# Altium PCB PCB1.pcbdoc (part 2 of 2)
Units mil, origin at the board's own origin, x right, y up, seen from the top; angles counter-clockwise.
Board outline 2401.6 x 2401.6 mil, 2 copper layers (Top Layer, Bottom Layer), stack 62.2 mil thick; 60 components, 46 nets, 313 pads, 160 vias.
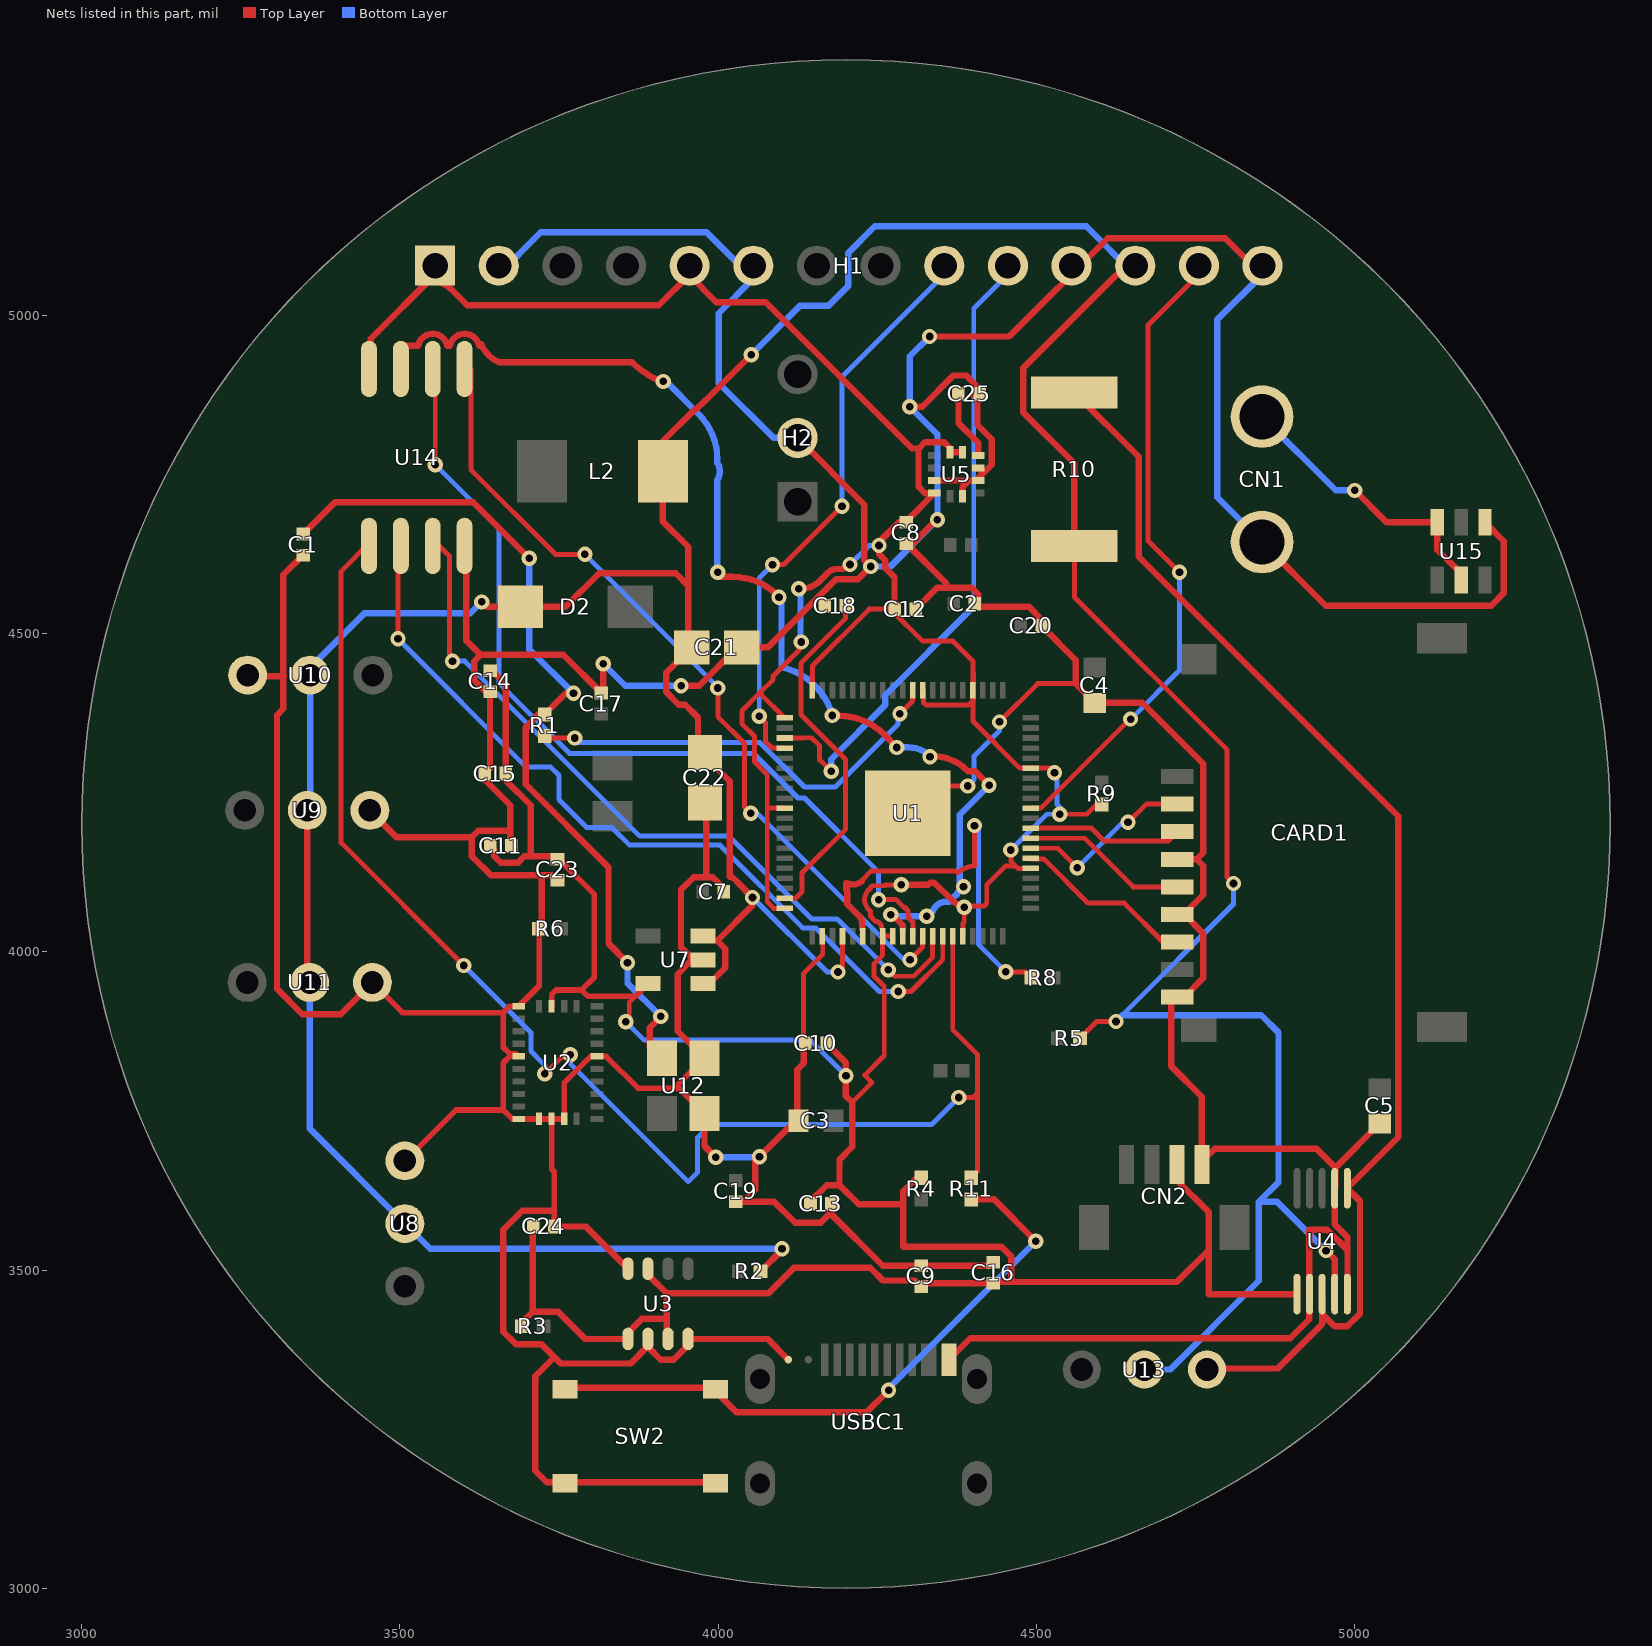
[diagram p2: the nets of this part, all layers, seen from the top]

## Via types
v1: diameter 24, hole 12, Top Layer to Bottom Layer, 160 vias

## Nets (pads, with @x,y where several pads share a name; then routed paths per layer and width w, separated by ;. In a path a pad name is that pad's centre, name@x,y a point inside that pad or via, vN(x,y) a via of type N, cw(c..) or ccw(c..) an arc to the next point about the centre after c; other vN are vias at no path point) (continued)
$1N402: H1.9 U1.44 | length 901.6
  Top Layer w7.8: v1(4064.5,4370.1) 4074.5,4360.1 4074.5,4330.1 4084.5,4320.1 U1.44@4104.5,4320.1 ; v1(4085.4,4608.2) 4102.5,4608.2 v1(4194.5,4700.1)
  Bottom Layer w7.8: v1(4064.5,4370.1) 4064.5,4587.2 v1(4085.4,4608.2) ; v1(4194.5,4700.1) 4194.5,4903.6 H1.9@4354.3,5063.4
$1N403: H1.10 U1.43 | length 1001.4
  Top Layer w7.8: U1.43@4104.5,4335.9 4131.5,4335.9 4131.9,4336.3 4146.6,4336.3 4159.4,4323.5 4159.4,4301.7 v1(4177.5,4283.6)
  Bottom Layer w7.8: 4401.5,4542.7 4401.5,5010.6 H1.10@4454.3,5063.4
  Bottom Layer w10: v1(4177.5,4283.6) 4177.5,4302.8 4262.5,4387.8 4262.5,4403.2 4398.6,4539.3 4398.6,4539.6 ccw(c4395.5,4542.7) 4399.9,4542.7
$1N404: H1.13 U1.11 | length 997.6
  Top Layer w7.8: U1.11@4490.9,4225.6 4506.6,4225.6 4646.6,4365.6 v1(4647.9,4365.6) ; v1(4724.8,4596.1) 4675.6,4645.3 4675.6,4984.7 H1.13@4754.3,5063.4
  Bottom Layer w7.8: v1(4647.9,4365.6) 4724.8,4442.6 v1(4724.8,4596.1)
$1N405: CARD1.5 U1.8 | length 262.2
  Top Layer w7.8: U1.8@4490.9,4178.4 4575.7,4178.4 4652,4102.1 CARD1.5@4721.5,4102.1
$1N406: CARD1.3 U1.9 | length 244.9
  Top Layer w7.8: U1.9@4490.9,4194.2 4586.5,4194.2 4606.5,4174.2 4707,4174.2 CARD1.3@4721.5,4188.7
$1N409: CARD1.2 U1.7 | length 284.9
  Top Layer w7.8: U1.7@4490.9,4162.7 4533.6,4162.7 v1(4564.3,4131.9) ; v1(4643.9,4203.4) 4672.5,4232 CARD1.2@4721.5,4232
  Bottom Layer w7.8: v1(4564.3,4131.9) 4635.7,4203.4 v1(4643.9,4203.4)
$1N413: R8.1 U1.66 | length 655.5
  Top Layer w7.8: U1.66@4225.3,4026.1 U1.66@4226.8,4024.6 ; 4225.3,4111.8 4240.6,4127.2 4373.4,4127.2 4376.3,4124.3 ; 4376.25,4124.23 cw(c4406.4,4088.3) 4402.31,4135.02 ; 4402.6,4135.1 v1(4402.6,4198.3) ; v1(4451.9,3968.6) 4483.3,3968.6 R8.1@4492.5,3959.4
  Top Layer w10: 4201.25,4108.11 ccw(c4211.3,4128.8) 4225.87,4111 ; 4201.3,4098.5 4201.3,4108.1 ; 4201.28,4098.56 cw(c4187.9,4092) 4202.8,4092 4202.8,4074.6 4221.6,4055.8 ; 4221.64,4055.84 cw(c4211.1,4045.3) 4225.9,4046.99 4226.2,4046.6 cw(c4225.3,4045.7) 4226.6,4045.7 U1.66@4226.6,4035.4
  Bottom Layer w7.8: v1(4402.6,4198.3) 4408.6,4192.3 4408.6,4012 v1(4451.9,3968.6)
$1N418: CN1.2 U15.3 U15.5 | length 450.2
  Top Layer w10: v1(4999.9,4724.9) 5049.9,4674.9 U15.3@5129.9,4674.9 5129.9,4631.8 5167.3,4594.4 U15.5@5167.3,4584.4
  Bottom Layer w10: CN1.2@4854.4,4840.7 4970.2,4724.9 v1(4999.9,4724.9)
$1N424: R1.1 U1.30 | length 691.8
  Top Layer w7.8: R1.1@3727.6,4338.9 3730.7,4335.8 v1(3774.5,4335.8) ; v1(4285.5,4374) 4305.5,4394 U1.30@4305.5,4411
  Bottom Layer w7.8: v1(3774.5,4335.8) 3781.3,4328.9 4065.5,4328.9 4135.5,4258.9 4183.8,4258.9 4282.7,4357.9 4282.7,4371.2 v1(4285.5,4374)
$1N425: C1.1 R1.2 U12.1 | length 1373.9
  Top Layer w10: C1.1@3347.9,4656.4 3397.9,4706.4 3615.3,4706.4 v1(3703.3,4618.4) ; v1(3772.8,4406) 3760.6,4406 R1.2@3727.6,4373 3717.6,4373 3697.6,4353 3697.6,4263 3827.6,4133 3827.6,4013 v1(3857.6,3983) ; v1(3909.8,3898.5) 3909.8,3898 3892.6,3880.8 3892.6,3851.7 U12.1@3911.5,3832.8
  Bottom Layer w10: v1(3703.3,4618.4) 3703.3,4475.6 v1(3772.8,4406) ; v1(3857.6,3983) 3857.6,3950.8 v1(3909.8,3898.5)
$1N433: C8.1 C9.1 C10.1 C11.1 C12.1 C13.1 C14.1 C15.1 C16.1 C23.1 C24.1 CN2.2 H1.1 H1.5 R3.2 R4.2 R9.2 U1.5 U1.15 U1.24 U1.29 U1.40 U1.41 U1.50 U1.60 U1.68 U1.69 U1.76 U2.4 U3.2 U3.6 U3.8 U4.6 U5.5 U5.6 U5.10 U7.5 U14.8 | length 7991
  Top Layer w7.8: v1(3854.9,3890) 3860.3,3895.3 3860.3,3920.7 3869.6,3930 ; U1.60@4104.2,4068.4 4087.1,4068.4 4077.1,4078.4 4077.1,4228.4 ; U1.50@4104.5,4225.6 4079.9,4225.6 4077.1,4228.4 ; U1.41@4104.5,4367.4 4067.1,4404.7 4067.1,4408.4 ; v1@4127,4486.3 4127,4473.8 4086.4,4433.2 4086.4,4427.6 4067.1,4408.4 ; U1.40@4148.1,4411 4148.1,4449.3 4237.1,4538.4 C12.1@4277.1,4538.4 4277.1,4532.1 4321.3,4488 4368.8,4488 4400,4456.8 4400,4439.2 ; 4210.6,3763.5 4241.4,3794.4 4241.4,3794.9 4230,3806.3 4260.9,3837.2 4260.9,3945.4 4245,3961.3 4245,3981.3 4258.3,3994.6 U1.68@4258.3,4024.6 ; 4239.3,4055.6 4239.3,4064.1 ; 4239.31,4064.05 cw(c4252,4081.9) 4239.31,4099.75 ; 4239.3,4099.8 4239.3,4101.2 4241.9,4103.8 4261.1,4103.8 4262.5,4105.2 v1(4287.5,4105.2) ; 4240.6,4054.6 4247.7,4047.5 ; 4247.73,4047.57 cw(c4246.9,4037.7) 4256.8,4037.7 ccw(c4261.8,4037.7) U1.68@4258.26,4034.16 ; U1.68@4256.8,4026.1 U1.68@4258.3,4024.6 ; U1.68@4258.2,4034.1 U1.68@4258.4,4033.9 ; U1.69@4274.1,4024.6 U1.68@4258.3,4024.6 ; U1.29@4321.3,4411 4322.6,4409.7 4322.6,4391.5 4326.1,4388 4393.5,4388 4400,4394.5 ; U1.76@4384.3,4024.6 4384.3,4044.6 4386.6,4046.9 v1(4386.6,4070) ; v1(4386.6,4070) ccw(c4389.9,4070.7) v1@4393.02,4072.05 ; v1@4393,4072.1 4418.1,4072.1 ; 4418.1,4072.04 ccw(c4404.5,4089.2) 4421.66,4075.6 ; 4421.9,4075.9 4421.9,4105.4 4451.6,4135.1 4466.9,4135.1 ; v1(4459.8,4159.9) 4459.8,4142.3 4466.9,4135.1 ; U1.5@4490.9,4131.2 4470.9,4131.2 4466.9,4135.1 ; v1(4528.4,4281.2) 4520.9,4288.6 U1.15@4490.9,4288.6 4473.9,4288.6 4400,4362.5 4400,4394.5 ; v1(4536.8,4216.1) 4579.1,4216.1 4598,4235 R9.2@4603.5,4235 ; 4067.1,4408.4 4037.1,4378.4 4037.1,4358.4 4057.1,4338.4 4057.1,4298.4 4077.1,4278.4 4077.1,4228.4 ; 4400,4394.5 U1.24@4400,4411 4400,4439.2 ; 4400,4394.5 4401.3,4395.8 4401.3,4438 4400,4439.2
  Top Layer w8.9: U2.4@3738.3,3914.5 3738.3,3932.7 3745.5,3940 3785.5,3940 ; C23.1@3747.6,4145.5 3755.5,4140 3805.5,4090 3805.5,3960 3785.5,3940 ; U7.5@3889.6,3950 3869.6,3930 3795.5,3930 3785.5,3940
  Top Layer w9.9: H1.5@3954.3,5063.4 3997.1,5020.6 4074.8,5020.6 4304.8,4790.6 4314.8,4790.6 ; C8.1@4295.8,4674.6 4295.8,4676.7 U5.10@4339.6,4720.6 4324.8,4720.6 4314.8,4730.6 4314.8,4790.6 ; U5.5@4383.9,4784.6 U5.6@4364.3,4784.6 4364.3,4791.2 4354.8,4800.6 4324.8,4800.6 4314.8,4790.6
  Top Layer w10: U14.8@3454.2,4922.9 3454.2,4963.3 H1.1@3554.3,5063.4 ; H1.1@3550.7,5053.2 cw(c3550.7,5010.6) 3580.82,5040.72 ; 3580.9,5040.7 3606,5015.6 ; 3606.4,5015.6 3906.4,5015.6 H1.5@3954.3,5063.4 ; C14.1@3641.6,4441.4 3645,4441.4 3666.2,4420.1 C15.1@3666.2,4280.1 3666.2,4269.2 3705.5,4230 3705.5,4150 ; C11.1@3641.7,4166.5 3648.2,4160 3648.2,4150 3658.2,4140 3685.5,4140 3695.5,4150 3705.5,4150 ; R3.2@3691.7,3411.5 3691.7,3417.9 3708.4,3434.6 ; C24.1@3709.3,3568.5 3708.4,3567.6 3708.4,3434.6 ; C23.1@3755.5,4140 3745.5,4150 3705.5,4150 ; U3.2@3889.8,3502.1 3889.8,3492.9 3919,3463.7 ; U3.6@3921.3,3391.8 3919,3394.2 3919,3423.7 ; v1@4125,4569.1 ccw(c4125,4620.5) 4161.35,4584.15 ; C13.1@4145,3604.5 4145,3607.9 4170.6,3633.5 4190.6,3633.5 ; 4161.3,4584.2 4173.9,4596.7 cw(c4185.2,4585.4) 4185.2,4601.4 4192.4,4601.4 ccw(c4192.4,4618.8) 4204.7,4606.5 v1@4206.9,4608.7 ; C10.1@4170.2,3856.4 4200.6,3826 4200.6,3773.5 4210.6,3763.5 4210.6,3693.5 4190.6,3673.5 4190.6,3633.5 ; C12.1@4277.1,4538.4 4277.1,4588.4 4262.7,4602.9 4262.7,4614.9 4252.6,4625 v1(4252.6,4638.4) 4252.6,4643.9 4283.4,4674.6 C8.1@4295.8,4674.6 ; v1(4287.5,4105.2) 4302.4,4105.2 4302.8,4105.6 4321.8,4105.6 4322.2,4105.2 4329.7,4105.2 4332.1,4107.7 ; R4.2@4319,3645.1 4312.1,3645.1 4290.6,3623.5 4290.6,3603.5 ; 4334,4108.7 4339.6,4108.7 4368.3,4080 ; 4368.27,4080.07 ccw(c4386.8,4098.6) v1@4386.8,4072.4 ; CN2.2@4720.5,3666 4720.5,3641.3 4770.5,3591.3 4770.5,3531.3 ; U4.6@4909.5,3462.3 4770.5,3462.3 4770.5,3531.3 ; 3708.4,3434.6 3748.4,3434.6 3791.1,3391.8 U3.8@3858.4,3391.8 3858.4,3401.8 3880.2,3423.7 3919,3423.7 ; 3919,3423.7 3919,3463.7 ; 3919,3463.7 4079,3463.7 4119,3503.7 4239,3503.7 4259,3483.7 4309,3483.7 C9.1@4319,3473.7 4324.6,3479.3 C16.1@4432.4,3479.3 4434.3,3481.3 4460.5,3481.3 ; 4190.6,3633.5 4220.6,3603.5 4290.6,3603.5 ; 4290.6,3603.5 4290.6,3536.7 4445.1,3536.7 4460.5,3521.3 4460.5,3481.3 ; 4460.5,3481.3 4720.5,3481.3 4770.5,3531.3
  Bottom Layer w7.8: v1(3854.9,3890) 3883.6,3861.3 4144.8,3861.3 v1(4200.7,3805.3) ; v1(4207.1,4608.4) 4237.1,4638.4 v1(4252.6,4638.4) ; v1(4459.8,4159.9) 4516,4216.1 v1(4536.8,4216.1) 4536.8,4227.5 4532.4,4231.8 4532.4,4277.2 v1(4528.4,4281.2)
  Bottom Layer w10: v1@4127.13,4568.43 cw(c4121.9,4563.2) v1@4129.3,4563.2 ; v1@4129.4,4486 v1@4129.4,4563.2
  other v1: 4130.7,4486.7 4126.7,4570.3
$1N435: R10.1 U4.1 U4.8 U13.1 | length 2063.9
  Top Layer w10: R10.1@4559.5,4878.8 4660.7,4777.6 4660.7,4620.6 5068.3,4213 5068.3,3708.5 U4.1@4988.3,3628.5 5008.3,3608.5 5008.3,3431.6 4988.3,3411.6 4968.3,3411.6 4948.9,3430.9 U4.8@4948.9,3462.3 4948.9,3415.4 4878.9,3345.4 4769.7,3345.4 U13.1@4768,3343.8
$1N438: R11.1 U1.75 U14.1 | length 2261.3
  Top Layer w7.8: U14.1@3454.2,4645 3407.7,4597.8 3407.7,4171.1 v1(3600.4,3978.4) ; v1(3727.7,3808.4) 3757.7,3838.4 v1(3767.7,3838.4) ; U1.75@4368.5,4024.6 4368.5,3877.6 4407.7,3838.4 4407.7,3778.4 ; v1(4378,3771.2) 4400.5,3771.2 4407.7,3778.4 ; R11.1@4397.7,3645.1 4407.7,3655.1 4407.7,3778.4
  Bottom Layer w7.8: v1(3600.4,3978.4) 3705.9,3872.9 3705.9,3843.8 3727.7,3821.9 v1(3727.7,3808.4) ; v1(3767.7,3838.4) 3767.7,3824.1 3952.9,3638.9 3967.7,3653.7 3967.7,3708.4 3987.7,3728.4 4335.2,3728.4 v1(4378,3771.2)
$1N439: R11.2 SW2.1 SW2.2 | length 1003.6
  Top Layer w10: SW2.1@3754.2,3312.8 3756.8,3315.4 3989.8,3315.4 4028.8,3276.4 4233.1,3276.4 v1(4267.7,3311) ; R11.2@4397.7,3611 4433.3,3611 v1(4498.9,3545.4)
  Bottom Layer w10: v1(4267.7,3311) 4267.7,3314.2 v1(4498.9,3545.4)
$1N444: C18.1 U1.59 | length 567.4
  Top Layer w7.8: U1.59@4104.5,4083.9 4121.5,4083.9 4131.5,4093.9 4131.5,4123.9 4200.3,4192.7 4200.3,4302.1 4130.3,4372.1 4130.3,4453.9 4200.3,4523.9 C18.1@4200.3,4543.7
$1N448: C21.1 C22.1 D2.1 H1.12 L2.2 R2.2 R5.1 R10.2 U1.64 U4.9 U7.1 U7.3 U8.2 U9.2 U10.2 U11.2 U13.2 | length 7115.7
  Top Layer w7.8: v1(4188.3,3968.2) 4195.3,3975.2 U1.64@4195.3,4024.6 ; R10.2@4559.5,4637.4 4559.5,4557.4 4799.5,4317.4 4799.5,4117.4 v1(4809.5,4107.4) ; R5.1@4568.3,3864.3 4594.5,3890.5 v1(4624.9,3890.5)
  Top Layer w10: U9.2@3354.4,4222.1 3354.4,3955.8 U11.2@3358.4,3951.8 ; v1(3628.6,4549.7) 3636.4,4541.9 D2.1@3689.2,4541.9 3760.1,4541.9 3813.1,4594.8 3933.1,4594.8 3953.1,4574.8 ; U7.1@3976.2,3950 3981,3954.8 3990.9,3954.8 4010.9,3974.8 4010.9,4004.8 3998.3,4017.4 4054,4073.1 v1(4054,4085.4) 4029.7,4109.7 4029.7,4109.9 4021.4,4118.2 4018.3,4118.2 4018.3,4268.2 C22.1@3968.3,4318.2 ; C22.1@3979.1,4313.1 3974,4318.2 C22.1@3968.3,4318.2 ; v1(4051.8,4938.2) 3979.4,4865.9 3979.3,4865.9 3965.8,4852.4 3963.6,4852.4 3913.1,4801.9 L2.2@3913.1,4754.8 3913.1,4676.1 3953.1,4636.1 3953.1,4483.5 C21.1@3958.3,4478.2 3918.3,4438.2 3918.3,4408.2 3938.3,4388.2 3948.3,4388.2 3968.3,4368.2 C22.1@3968.3,4318.2 ; R2.2@4066.7,3498.2 4100.2,3531.6 v1(4100.2,3533.4) ; R10.2@4559.5,4637.4 4559.5,4767.3 4479.5,4847.3 4479.5,4917.3 4625.5,5063.4 H1.12@4654.3,5063.4 ; v1(4954.8,3530.6) 4968.6,3516.8 U4.9@4968.6,3462.3
  Bottom Layer w7.8: v1(4054,4085.4) 4171.2,3968.2 v1(4188.3,3968.2) ; 4634.6,3900.1 4809.5,4075 v1(4809.5,4107.4)
  Bottom Layer w10: U9.2@3354.4,4222.1 3359.1,4226.7 3359.1,4446.6 3444.4,4531.9 3610.7,4531.9 v1(3628.6,4549.7) ; U11.2@3358.4,3951.8 3358.4,3722.5 U8.2@3507.8,3573 3547.4,3533.4 v1(4100.2,3533.4) ; v1(4051.8,4938.2) 4128.6,5015.1 4173.3,5015.1 4204.3,5046 4204.3,5097.9 4246.1,5139.7 4578,5139.7 H1.12@4654.3,5063.4 ; v1(4624.9,3890.5) 4634.6,3900.1 4853.3,3900.1 4880.2,3873.2 4880.2,3638.1 4849.5,3607.4 ; U13.2@4669.6,3343.8 4710.1,3343.8 4849.5,3483.2 4849.5,3607.4 ; v1(4954.8,3530.6) 4878,3607.4 4849.5,3607.4
$1N449: U1.74 U14.2 | length 1321.7
  Top Layer w7.8: v1(3496.9,4491.9) 3496.9,4637.7 U14.2@3504.2,4645 ; v1(4282.8,3937.6) 4302.8,3937.6 4352.8,3987.6 U1.74@4352.8,4024.6
  Bottom Layer w7.8: v1(3496.9,4491.9) 3698.7,4290.1 3736.9,4290.1 3749.8,4277.2 3749.8,4239 3793.4,4195.4 3833,4195.4 3860.8,4167.6 4002.8,4167.6 4132.8,4037.6 4152.8,4037.6 4252.8,3937.6 v1(4282.8,3937.6)
$1N450: U1.73 U14.3 | length 1205
  Top Layer w7.8: U14.3@3554.2,4645 3578.2,4621 3578.2,4461.1 v1(3582.6,4456.7) ; v1(4267,3971.6) 4277,3961.6 4307,3961.6 4337,3991.6 U1.73@4337,4024.6
  Bottom Layer w7.8: v1(3582.6,4456.7) 3601.9,4456.7 3877,4181.6 4017,4181.6 4147,4051.6 4187,4051.6 v1(4267,3971.6)
$1N451: U1.72 U14.5 | length 1308.1
  Top Layer w7.8: U14.5@3604.2,4922.9 3611.3,4915.8 3611.3,4757.6 3744.5,4624.4 v1(3790.6,4624.4) ; v1(3999.5,4414.4) 3999.5,4369.4 4041.3,4327.6 4041.3,4227.6 v1(4051.3,4217.6) ; v1(4301.3,3987.6) 4321.3,4007.6 U1.72@4321.3,4024.6
  Bottom Layer w7.8: v1(3790.6,4624.4) 3999.5,4415.5 v1(3999.5,4414.4) ; v1(4051.3,4217.6) 4061.3,4217.6 4291.3,3987.6 v1(4301.3,3987.6)
$1N452: U1.71 U14.6 | length 1408
  Top Layer w7.8: U14.6@3554.2,4922.9 3555.5,4921.6 v1(3555.5,4765.4) ; v1(4252,4081.9) 4279.5,4081.9 4289,4072.5 ; 4294.3,4069.6 4293,4069.6 ; U1.71@4305.5,4024.6 4305.9,4024.9 4305.9,4046.8 4298.1,4054.6 4298.1,4064.5 4293,4069.6 ; 4289,4072.5 4293,4069.6 ; 4289,4072.5 4291.9,4069.6 4293,4069.6
  Bottom Layer w7.8: v1(3555.5,4765.4) 3655.5,4665.4 3655.5,4422.6 3766.6,4311.6 4055.5,4311.6 4125.5,4241.6 4135.5,4241.6 4252,4125.1 v1(4252,4081.9)
$1N453: U1.70 U14.7 | length 1761.3
  Top Layer w10: U14.7@3498.95,4949.35 cw(c3505.6,4942.7) 3505.6,4952.1 3528.5,4952.1 ; 3528.54,4952.11 cw(c3551.5,4947.6) 3574.46,4952.11 ; 3574.4,4952.1 3578.5,4952.1 ; 3578.54,4952.11 cw(c3601.5,4947.6) 3624.46,4952.11 ; 3624.4,4952.1 3627.8,4952.1 ; 3627.58,4954.79 ccw(c3675.9,4974.8) 3655.89,4926.48 3864.6,4926.5 ccw(c3962.8,5024.7) v1@3908.53,4896.84 ; v1@4003.2,4589 4023.3,4589 cw(c4023.3,4490.1) v1@4093.23,4560.03 ; v1@4176.2,4370.6 4190.4,4370.6 cw(c4190.4,4270.6) 4261.11,4341.31 4280.7,4321.6 v1(4280.7,4321) ; v1(4271,4058.5) 4273.1,4058.5 4289.8,4041.8 U1.70@4289.8,4033 ; v1@4334.3,4307.9 cw(c4334.3,4225.1) 4392.85,4283.65 ; 4392.9,4283.6 4403.7,4283.6 v1(4425.6,4261.7)
  Bottom Layer w10: v1@3916.5,4897.7 3969.4,4844.7 cw(c3898.7,4774) 3998.7,4774 3998.7,4767.8 cw(c3979.7,4754.8) 3998.68,4741.81 3998.7,4596.6 v1(3999.3,4596.1) ; 4099.4,4447.2 v1@4099.4,4559.3 ; 4099.43,4447.21 cw(c4076,4342.4) 4112.03,4443.58 cw(c4076,4342.4) 4120.2,4440.28 cw(c4076,4342.4) v1(4179.4,4371.3) ; v1(4271,4058.5) 4273.8,4055.7 v1(4327.8,4055.7) 4329.2,4055.7 v1@4335.6,4062.1 ; v1@4283,4321.2 4298.3,4321.2 ; 4298.3,4321.3 cw(c4298.3,4271.3) v1@4333.66,4306.66 ; v1@4336.93,4063.42 cw(c4358.6,4055.7) 4363.34,4078.21 ; 4363.3,4078.2 4366.8,4081.6 ; 4366.72,4081.57 cw(c4386.6,4070) 4375.03,4089.88 ; 4375.1,4089.9 4375.1,4092.1 v1(4385.3,4102.4) 4379.6,4108.2 4379.6,4215.6 v1(4425.6,4261.7)
  other v1: 4332.8,4306.6 4095.5,4556.9 3913.5,4896.1
$1N456: C25.1 U5.4 | length 110.2
  Top Layer w9.9: C25.1@4377.5,4877 4377.5,4830.7 4408.5,4799.6 U5.4@4408.5,4779.6
$1N457: C1.2 C2.2 C3.2 C4.2 C5.2 C7.2 C8.2 C9.2 C10.2 C11.2 C12.2 C13.2 C14.2 C15.2 C16.2 C17.2 C18.2 C19.2 C20.2 C21.2 C22.2 C23.2 C24.2 C25.2 CARD1.4 CARD1.6 CARD1.9 CN1.1 CN2.1 H1.2 H1.6 H1.11 H1.14 H2.2 R6.2 SW2.3 SW2.4 U1.62 U1.81 U2.6 U2.10 U2.15 U2.16 U2.17 U2.18 U2.25 U3.1 U3.5 U3.7 U4.2 U4.7 U4.10 U5.2 U5.3 U5.9 U5.12 U7.2 U8.3 U9.3 U10.3 U11.3 U12.3 U12.4 U14.4 U15.1 USBC1.A1B12 USBC1.B1A12 | length 14127.4
  Top Layer w7.8: C10.2@4134.3,3846.2 4134.3,3966.2 4164.3,3996.2 4164.3,4024.1 U1.62@4163.8,4024.6 ; U1.81@4297.7,4217.8 4340.5,4260.6 v1(4392.1,4260.6) ; v1(4441.9,4361.2) 4501.9,4421.2 4561.9,4421.2
  Top Layer w8.9: U11.3@3456.8,3951.8 3504.1,3904.5 3662.3,3904.5 ; U8.3@3507.8,3671.4 3588.1,3751.6 3662.3,3751.6 ; R6.2@3718.8,4036.2 3718.8,3946.7 U2.6@3686.6,3914.5 3672.3,3914.5 3662.3,3904.5 ; C24.2@3742.4,3568.5 3742.4,3654.5 3738.3,3658.6 U2.17@3738.3,3737.4 ; U12.4@3978.4,3832.8 3933.9,3788.3 3933.9,3785.8 3873.9,3785.8 3823.9,3835.8 U2.25@3809.6,3835.8 3799.6,3835.8 3758,3794.1 U2.18@3758,3737.4 U2.17@3738.3,3737.4 ; 3662.3,3751.6 3662.3,3825.8 3672.3,3835.8 U2.10@3686.6,3835.8 3682.3,3840 3672.3,3840 3662.3,3850 3662.3,3904.5 ; 3662.3,3751.6 3676.6,3737.4 U2.15@3686.6,3737.4 U2.16@3718.6,3737.4 U2.17@3738.3,3737.4
  Top Layer w9.9: H2.2@4124.8,4807.4 4229.6,4702.5 4229.6,4615.4 v1(4239.6,4605.4) ; C8.2@4295.8,4641.5 4305.8,4641.5 4335.8,4671.5 4337,4671.5 v1(4344.4,4679) ; v1(4301,4856.3) 4320.5,4856.3 4369.6,4905.4 4389.6,4905.4 4407.3,4887.8 C25.2@4407.3,4875.4 ; U5.9@4339.6,4740.3 4404.5,4740.3 4429.6,4765.4 4429.6,4805.4 4407.3,4827.8 C25.2@4407.3,4875.4 ; U5.12@4383.7,4715.9 4383.7,4730.3 4393.7,4740.3 U5.2@4408.5,4740.3 U5.2@4409.6,4745.4 ; 4399.6,4875.4 C25.2@4407.3,4875.4 ; U5.3@4408.5,4760 4413.1,4755.4 4419.6,4755.4 ; C25.2@4410.6,4877 4409,4875.4 C25.2@4407.3,4875.4
  Top Layer w10: U10.3@3260.7,4446.6 3274.3,4433 3316.8,4433 ; 3317.6,4433 3316.8,4433 ; C1.2@3347.9,4623.3 3316.8,4592.2 3316.8,4433 ; U9.3@3452.8,4222.1 3494.7,4180.1 3613.1,4180.1 ; U11.3@3456.8,3951.8 3406.8,3901.8 3346.8,3901.8 3306.8,3941.8 3306.8,4371.8 3316.8,4381.8 3316.8,4433 ; U14.4@3604.2,4645 3604.2,4489 3626.6,4466.6 ; 3673.1,4190.1 3623.1,4190.1 3613.1,4180.1 ; C11.2@3674.8,4166.5 3673.1,4168.1 3673.1,4230.1 3633.1,4270.1 C15.2@3633.1,4280.1 3641.6,4288.6 C14.2@3641.6,4408.3 3634.9,4408.3 3616.6,4426.6 3616.6,4456.6 3626.6,4466.6 ; R6.2@3718.8,4036.2 3723.1,4040.5 3723.1,4120.1 ; 3742.4,3363.3 3712.4,3333.3 3712.4,3184.5 3730.5,3166.4 4000.8,3166.4 SW2.4@4001.7,3165.5 ; C24.2@3742.4,3568.5 3792,3568.5 U3.1@3858.4,3502.1 ; 3742.4,3593.3 3692.4,3593.3 3662.4,3563.3 3662.4,3403.3 3682.4,3383.3 3722.4,3383.3 3752.4,3353.3 3862.4,3353.3 3889.8,3380.8 U3.7@3889.8,3391.8 3889.8,3379.1 3909.8,3359.1 3929.8,3359.1 3949.8,3379.1 3949.8,3388.9 U3.5@3952.8,3391.8 4077.8,3391.8 USBC1.A1B12@4110.3,3359.3 ; C23.2@3747.6,4112.4 3739.9,4120.1 3643.1,4120.1 3613.1,4150.1 3613.1,4180.1 ; v1(3819.4,4452.7) 3819.4,4409.5 C17.2@3816.6,4406.6 3756.6,4466.6 3626.6,4466.6 ; 3933.9,3785.8 3938.8,3785.8 U12.3@3978.4,3746.2 3978.4,3695 v1(3996.1,3677.3) ; v1(3941.7,4418.2) 3970.1,4418.2 4030.1,4478.2 C21.2@4037.1,4478.2 4078,4478.2 4185.2,4585.4 4219.6,4585.4 v1(4239.6,4605.4) ; U12.4@3978.4,3832.8 3936.2,3875 3936.2,3965 3958.6,3987.4 U7.2@3976.2,3987.4 3961.5,3987.4 3941.5,4007.4 3941.5,4097.4 3961.5,4117.4 3991.5,4117.4 4008.9,4100 C7.2@4008.9,4094.7 ; C22.2@3979.1,4234.4 3981.5,4231.9 3981.5,4117.4 ; C19.2@4027.6,3607.6 4039.8,3607.6 ; C3.2@4126.1,3734.4 C3.2@4124.3,3736.2 ; C10.2@4137.1,3856.4 4134.3,3853.6 4134.3,3824.9 4124.3,3814.9 C3.2@4124.3,3736.2 ; C13.2@4178,3604.5 4178,3591.7 ; C8.2@4295.8,4641.5 4358.3,4579.1 4358.3,4571.9 ; C12.2@4310.2,4538.4 4343.7,4571.9 4398.3,4571.9 4408.3,4561.9 C2.2@4408.3,4541.9 ; v1(4332.1,4966.6) 4457.5,4966.6 4612,5121.2 4796.5,5121.2 H1.14@4854.3,5063.4 ; USBC1.B1A12@4362.3,3359.3 4395.9,3393 4898.6,3393 4928.6,3423 U4.7@4928.6,3463 ; C2.2@4403.4,4546.8 C2.2@4408.3,4541.9 ; C16.2@4432.4,3512.4 4426.8,3506.8 C9.2@4319,3506.8 4258.5,3506.8 4178,3587.3 4178,3591.7 ; CARD1.4@4721.5,4145.4 4752.1,4145.4 ; CN2.1@4759.9,3666 CN2.1@4759.9,3670.5 ; CN1.1@4854.4,4643.8 4954.4,4543.8 5214.4,4543.8 5234.4,4563.8 5234.4,4645.2 U15.1@5204.7,4674.9 ; U4.7@4929.2,3462.3 U4.7@4928.6,3463 ; U4.10@4988.3,3462.3 4988.6,3462.6 4988.6,3531.6 ; C5.2@5039.5,3730.4 4969.9,3660.9 4969.9,3660.5 ; 4039.8,3607.6 4058.4,3626.2 4058.4,3671.6 v1(4064.9,3678.1) 4123,3736.2 C3.2@4124.3,3736.2 ; 4039.8,3607.6 4087.6,3607.6 4120.8,3574.5 4160.8,3574.5 4178,3591.7 ; C2.2@4408.3,4541.9 4488.3,4541.9 4508.3,4521.9 C20.2@4508.3,4511.9 4561.9,4458.2 4561.9,4421.2 C4.2@4591.9,4391.2 4666.2,4391.2 4762.1,4295.4 4762.1,4155.4 4752.1,4145.4 ; 4752.1,4145.4 4762.1,4135.4 4762.1,4089.4 4731.5,4058.8 CARD1.6@4721.5,4058.8 4732.1,4058.8 4762.1,4028.8 4762.1,3958.8 4732.1,3928.8 CARD1.9@4721.5,3928.9 4711.5,3918.9 4711.5,3820.6 4759.9,3772.1 CN2.1@4759.9,3670.5 ; CN2.1@4759.9,3670.5 4779.9,3690.5 4939.9,3690.5 4969.9,3660.5 ; U4.7@4928.6,3463 4928.6,3563.3 4956.8,3563.3 4988.6,3531.6 ; 4969.9,3660.5 4969.9,3629.8 U4.2@4968.6,3628.5 4968.6,3571.6 4988.6,3551.6 4988.6,3531.6
  Bottom Layer w7.8: v1(4392.1,4260.6) 4402,4270.5 4402,4307.3 4441.9,4347.2 v1(4441.9,4361.2)
  Bottom Layer w9.9: v1(4301,4856.3) 4344.4,4812.9 v1(4344.4,4679)
  Bottom Layer w10: H1.2@3654.3,5063.4 3721.4,5130.5 3981.7,5130.5 H1.6@4054.8,5057.4 ; v1(3819.4,4452.7) 3853.9,4418.2 v1(3941.7,4418.2) ; v1(3996.1,3677.3) 4064.1,3677.3 v1(4064.9,3678.1) ; H1.6@4054.3,5063.4 H1.6@4054.8,5057.4 ; H2.2@4124.8,4807.4 4086.9,4807.4 4000.8,4893.5 4000.8,5003.4 H1.6@4054.8,5057.4 ; v1(4239.6,4605.4) 4270.8,4605.4 v1(4344.4,4679) ; v1(4301,4856.3) 4301,4935.6 v1(4332.1,4966.6) ; H1.14@4854.3,5063.4 4784.3,4993.4 4784.3,4713.9 CN1.1@4854.4,4643.8
$1N460: CARD1.7 U1.6 | length 285.1
  Top Layer w7.8: U1.6@4490.9,4146.9 4492.3,4145.5 4512,4145.5 4581,4076.4 4638,4076.4 4698.9,4015.5 CARD1.7@4721.5,4015.5
pads on no net: CARD1.1 CARD1.8 CARD1.10 CARD1.11 CARD1.12 CARD1.13 CN2.0 U1.3 U1.4 U1.12 U1.13 U1.14 U1.16 U1.17 U1.18 U1.19 U1.20 U1.21 U1.22 U1.23 U1.25 U1.26 U1.27 U1.28 U1.35 U1.36 U1.37 U1.38 U1.39 U1.42 U1.47 U1.48 U1.49 U1.52 U1.53 U1.54 U1.55 U1.56 U1.57 U1.58 U2.1 U2.2 U2.3 U2.5 U2.7 U2.8 U2.9 U2.12 U2.13 U2.14 U2.21 U2.22 U2.23 U2.24 U2.26 U2.27 U2.28 U4.3 U5.7 U5.8 U7.4 U13.3 USBC1.1 USBC1.2 USBC1.3 USBC1.4 USBC1.A5 USBC1.A7 USBC1.B5 USBC1.B6 USBC1.B7 USBC1.B8

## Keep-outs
Board Outline Layer:
  region: 3348,4782.3 3347.6,4775.5 3346.5,4768.7 3344.5,4762.1 3341.9,4755.8 3338.5,4749.8 3334.5,4744.3 3329.8,4739.3 3324.7,4734.8 3319,4730.9 3312.9,4727.7 3306.5,4725.2 3299.9,4723.5 3293.1,4722.5 3286.3,4722.3 3279.4,4722.9 3272.7,4724.2 3266.2,4726.4 3260,4729.2 3254.1,4732.7 3248.7,4736.9 3243.8,4741.7 3239.4,4747 3235.7,4752.8 3232.7,4758.9 3230.4,4765.4 3228.8,4772.1 3228,4778.9 3228,4785.7 3228.8,4792.5 3230.4,4799.2 3232.7,4805.7 3235.7,4811.8 3239.4,4817.6 3243.8,4822.9 3248.7,4827.7 3254.1,4831.9 3260,4835.4 3266.2,4838.3 3272.7,4840.4 3279.4,4841.7 3286.3,4842.3 3293.1,4842.1 3299.9,4841.2 3306.5,4839.4 3312.9,4836.9 3319,4833.7 3324.7,4829.9 3329.8,4825.4 3334.5,4820.3 3338.5,4814.8 3341.9,4808.8 3344.5,4802.5 3346.5,4795.9 3347.6,4789.2
  region: 3348,4782.3 3347.6,4775.5 3346.5,4768.7 3344.5,4762.1 3341.9,4755.8 3338.5,4749.8 3334.5,4744.3 3329.8,4739.3 3324.7,4734.8 3319,4730.9 3312.9,4727.7 3306.5,4725.2 3299.9,4723.5 3293.1,4722.5 3286.3,4722.3 3279.4,4722.9 3272.7,4724.2 3266.2,4726.4 3260,4729.2 3254.1,4732.7 3248.7,4736.9 3243.8,4741.7 3239.4,4747 3235.7,4752.8 3232.7,4758.9 3230.4,4765.4 3228.8,4772.1 3228,4778.9 3228,4785.7 3228.8,4792.5 3230.4,4799.2 3232.7,4805.7 3235.7,4811.8 3239.4,4817.6 3243.8,4822.9 3248.7,4827.7 3254.1,4831.9 3260,4835.4 3266.2,4838.3 3272.7,4840.4 3279.4,4841.7 3286.3,4842.3 3293.1,4842.1 3299.9,4841.2 3306.5,4839.4 3312.9,4836.9 3319,4833.7 3324.7,4829.9 3329.8,4825.4 3334.5,4820.3 3338.5,4814.8 3341.9,4808.8 3344.5,4802.5 3346.5,4795.9 3347.6,4789.2
  region: 5179,4801.7 5178.6,4794.8 5177.4,4788.1 5175.5,4781.5 5172.8,4775.2 5169.4,4769.2 5165.4,4763.7 5160.8,4758.6 5155.6,4754.1 5149.9,4750.2 5143.9,4747 5137.5,4744.6 5130.9,4742.8 5124.1,4741.8 5117.2,4741.6 5110.4,4742.2 5103.7,4743.6 5097.2,4745.7 5090.9,4748.6 5085,4752.1 5079.6,4756.3 5074.7,4761.1 5070.4,4766.4 5066.7,4772.1 5063.6,4778.3 5061.3,4784.7 5059.8,4791.4 5059,4798.2 5059,4805.1 5059.8,4811.9 5061.3,4818.6 5063.6,4825 5066.7,4831.2 5070.4,4837 5074.7,4842.3 5079.6,4847 5085,4851.2 5090.9,4854.8 5097.2,4857.6 5103.7,4859.7 5110.4,4861.1 5117.2,4861.7 5124.1,4861.5 5130.9,4860.5 5137.5,4858.8 5143.9,4856.3 5149.9,4853.1 5155.6,4849.2 5160.8,4844.7 5165.4,4839.7 5169.4,4834.1 5172.8,4828.2 5175.5,4821.8 5177.4,4815.3 5178.6,4808.5
  region: 5179,4801.7 5178.6,4794.8 5177.4,4788.1 5175.5,4781.5 5172.8,4775.2 5169.4,4769.2 5165.4,4763.7 5160.8,4758.6 5155.6,4754.1 5149.9,4750.2 5143.9,4747 5137.5,4744.6 5130.9,4742.8 5124.1,4741.8 5117.2,4741.6 5110.4,4742.2 5103.7,4743.6 5097.2,4745.7 5090.9,4748.6 5085,4752.1 5079.6,4756.3 5074.7,4761.1 5070.4,4766.4 5066.7,4772.1 5063.6,4778.3 5061.3,4784.7 5059.8,4791.4 5059,4798.2 5059,4805.1 5059.8,4811.9 5061.3,4818.6 5063.6,4825 5066.7,4831.2 5070.4,4837 5074.7,4842.3 5079.6,4847 5085,4851.2 5090.9,4854.8 5097.2,4857.6 5103.7,4859.7 5110.4,4861.1 5117.2,4861.7 5124.1,4861.5 5130.9,4860.5 5137.5,4858.8 5143.9,4856.3 5149.9,4853.1 5155.6,4849.2 5160.8,4844.7 5165.4,4839.7 5169.4,4834.1 5172.8,4828.2 5175.5,4821.8 5177.4,4815.3 5178.6,4808.5
  region: 3356.3,3622.1 3355.9,3615.3 3354.7,3608.5 3352.8,3601.9 3350.1,3595.6 3346.7,3589.7 3342.7,3584.1 3338.1,3579.1 3332.9,3574.6 3327.2,3570.7 3321.2,3567.5 3314.8,3565 3308.1,3563.3 3301.4,3562.3 3294.5,3562.1 3287.7,3562.7 3281,3564.1 3274.4,3566.2 3268.2,3569 3262.3,3572.6 3256.9,3576.7 3252,3581.5 3247.6,3586.8 3243.9,3592.6 3240.9,3598.7 3238.6,3605.2 3237.1,3611.9 3236.3,3618.7 3236.3,3625.5 3237.1,3632.4 3238.6,3639 3240.9,3645.5 3243.9,3651.6 3247.6,3657.4 3252,3662.7 3256.9,3667.5 3262.3,3671.7 3268.2,3675.2 3274.4,3678.1 3281,3680.2 3287.7,3681.6 3294.5,3682.1 3301.4,3681.9 3308.1,3681 3314.8,3679.2 3321.2,3676.7 3327.2,3673.5 3332.9,3669.7 3338.1,3665.2 3342.7,3660.1 3346.7,3654.6 3350.1,3648.6 3352.8,3642.3 3354.7,3635.7 3355.9,3629
  region: 3356.3,3622.1 3355.9,3615.3 3354.7,3608.5 3352.8,3601.9 3350.1,3595.6 3346.7,3589.7 3342.7,3584.1 3338.1,3579.1 3332.9,3574.6 3327.2,3570.7 3321.2,3567.5 3314.8,3565 3308.1,3563.3 3301.4,3562.3 3294.5,3562.1 3287.7,3562.7 3281,3564.1 3274.4,3566.2 3268.2,3569 3262.3,3572.6 3256.9,3576.7 3252,3581.5 3247.6,3586.8 3243.9,3592.6 3240.9,3598.7 3238.6,3605.2 3237.1,3611.9 3236.3,3618.7 3236.3,3625.5 3237.1,3632.4 3238.6,3639 3240.9,3645.5 3243.9,3651.6 3247.6,3657.4 3252,3662.7 3256.9,3667.5 3262.3,3671.7 3268.2,3675.2 3274.4,3678.1 3281,3680.2 3287.7,3681.6 3294.5,3682.1 3301.4,3681.9 3308.1,3681 3314.8,3679.2 3321.2,3676.7 3327.2,3673.5 3332.9,3669.7 3338.1,3665.2 3342.7,3660.1 3346.7,3654.6 3350.1,3648.6 3352.8,3642.3 3354.7,3635.7 3355.9,3629
  region: 5187.2,3641.5 5186.8,3634.6 5185.6,3627.9 5183.7,3621.3 5181,3615 5177.7,3609 5173.6,3603.5 5169,3598.4 5163.8,3593.9 5158.2,3590.1 5152.1,3586.9 5145.7,3584.4 5139.1,3582.6 5132.3,3581.6 5125.4,3581.5 5118.6,3582 5111.9,3583.4 5105.4,3585.5 5099.1,3588.4 5093.3,3591.9 5087.8,3596.1 5082.9,3600.9 5078.6,3606.2 5074.9,3611.9 5071.9,3618.1 5069.6,3624.6 5068,3631.2 5067.2,3638 5067.2,3644.9 5068,3651.7 5069.6,3658.4 5071.9,3664.8 5074.9,3671 5078.6,3676.8 5082.9,3682.1 5087.8,3686.8 5093.3,3691 5099.1,3694.6 5105.4,3697.4 5111.9,3699.5 5118.6,3700.9 5125.4,3701.5 5132.3,3701.3 5139.1,3700.3 5145.7,3698.6 5152.1,3696.1 5158.2,3692.9 5163.8,3689 5169,3684.5 5173.6,3679.5 5177.7,3673.9 5181,3668 5183.7,3661.6 5185.6,3655.1 5186.8,3648.3
  region: 5187.2,3641.5 5186.8,3634.6 5185.6,3627.9 5183.7,3621.3 5181,3615 5177.7,3609 5173.6,3603.5 5169,3598.4 5163.8,3593.9 5158.2,3590.1 5152.1,3586.9 5145.7,3584.4 5139.1,3582.6 5132.3,3581.6 5125.4,3581.5 5118.6,3582 5111.9,3583.4 5105.4,3585.5 5099.1,3588.4 5093.3,3591.9 5087.8,3596.1 5082.9,3600.9 5078.6,3606.2 5074.9,3611.9 5071.9,3618.1 5069.6,3624.6 5068,3631.2 5067.2,3638 5067.2,3644.9 5068,3651.7 5069.6,3658.4 5071.9,3664.8 5074.9,3671 5078.6,3676.8 5082.9,3682.1 5087.8,3686.8 5093.3,3691 5099.1,3694.6 5105.4,3697.4 5111.9,3699.5 5118.6,3700.9 5125.4,3701.5 5132.3,3701.3 5139.1,3700.3 5145.7,3698.6 5152.1,3696.1 5158.2,3692.9 5163.8,3689 5169,3684.5 5173.6,3679.5 5177.7,3673.9 5181,3668 5183.7,3661.6 5185.6,3655.1 5186.8,3648.3
  lines w0.1: 3228,4778.9 3228.8,4772.1 3230.4,4765.4 3232.7,4758.9 3235.7,4752.8 3239.4,4747 3243.8,4741.7 3248.7,4736.9 3254.1,4732.7 3260,4729.2 3266.2,4726.4 3272.7,4724.2 3279.4,4722.9 3286.3,4722.3 3293.1,4722.5 3299.9,4723.5 3306.5,4725.2 3312.9,4727.7 3319,4730.9 3324.7,4734.8 3329.8,4739.3 3334.5,4744.3 3338.5,4749.8 3341.9,4755.8 3344.5,4762.1 3346.5,4768.7 3347.6,4775.5 3348,4782.3 3347.6,4789.2 3346.5,4795.9 3344.5,4802.5 3341.9,4808.8 3338.5,4814.8 3334.5,4820.3 3329.8,4825.4 3324.7,4829.9 3319,4833.7 3312.9,4836.9 3306.5,4839.4 3299.9,4841.2 3293.1,4842.1 3286.3,4842.3 3279.4,4841.7 3272.7,4840.4 3266.2,4838.3 3260,4835.4 3254.1,4831.9 3248.7,4827.7 3243.8,4822.9 3239.4,4817.6 3235.7,4811.8 3232.7,4805.7 3230.4,4799.2 3228.8,4792.5 3228,4785.7 3228,4778.9 ; 3236.3,3618.7 3237.1,3611.9 3238.6,3605.2 3240.9,3598.7 3243.9,3592.6 3247.6,3586.8 3252,3581.5 3256.9,3576.7 3262.3,3572.6 3268.2,3569 3274.4,3566.2 3281,3564.1 3287.7,3562.7 3294.5,3562.1 3301.4,3562.3 3308.1,3563.3 3314.8,3565 3321.2,3567.5 3327.2,3570.7 3332.9,3574.6 3338.1,3579.1 3342.7,3584.1 3346.7,3589.7 3350.1,3595.6 3352.8,3601.9 3354.7,3608.5 3355.9,3615.3 3356.3,3622.1 3355.9,3629 3354.7,3635.7 3352.8,3642.3 3350.1,3648.6 3346.7,3654.6 3342.7,3660.1 3338.1,3665.2 3332.9,3669.7 3327.2,3673.5 3321.2,3676.7 3314.8,3679.2 3308.1,3681 3301.4,3681.9 3294.5,3682.1 3287.7,3681.6 3281,3680.2 3274.4,3678.1 3268.2,3675.2 3262.3,3671.7 3256.9,3667.5 3252,3662.7 3247.6,3657.4 3243.9,3651.6 3240.9,3645.5 3238.6,3639 3237.1,3632.4 3236.3,3625.5 3236.3,3618.7 ; 5059,4798.2 5059.8,4791.4 5061.3,4784.7 5063.6,4778.3 5066.7,4772.1 5070.4,4766.4 5074.7,4761.1 5079.6,4756.3 5085,4752.1 5090.9,4748.6 5097.2,4745.7 5103.7,4743.6 5110.4,4742.2 5117.2,4741.6 5124.1,4741.8 5130.9,4742.8 5137.5,4744.6 5143.9,4747 5149.9,4750.2 5155.6,4754.1 5160.8,4758.6 5165.4,4763.7 5169.4,4769.2 5172.8,4775.2 5175.5,4781.5 5177.4,4788.1 5178.6,4794.8 5179,4801.7 5178.6,4808.5 5177.4,4815.3 5175.5,4821.8 5172.8,4828.2 5169.4,4834.1 5165.4,4839.7 5160.8,4844.7 5155.6,4849.2 5149.9,4853.1 5143.9,4856.3 5137.5,4858.8 5130.9,4860.5 5124.1,4861.5 5117.2,4861.7 5110.4,4861.1 5103.7,4859.7 5097.2,4857.6 5090.9,4854.8 5085,4851.2 5079.6,4847 5074.7,4842.3 5070.4,4837 5066.7,4831.2 5063.6,4825 5061.3,4818.6 5059.8,4811.9 5059,4805.1 5059,4798.2 ; 5067.2,3638 5068,3631.2 5069.6,3624.6 5071.9,3618.1 5074.9,3611.9 5078.6,3606.2 5082.9,3600.9 5087.8,3596.1 5093.3,3591.9 5099.1,3588.4 5105.4,3585.5 5111.9,3583.4 5118.6,3582 5125.4,3581.5 5132.3,3581.6 5139.1,3582.6 5145.7,3584.4 5152.1,3586.9 5158.2,3590.1 5163.8,3593.9 5169,3598.4 5173.6,3603.5 5177.7,3609 5181,3615 5183.7,3621.3 5185.6,3627.9 5186.8,3634.6 5187.2,3641.5 5186.8,3648.3 5185.6,3655.1 5183.7,3661.6 5181,3668 5177.7,3673.9 5173.6,3679.5 5169,3684.5 5163.8,3689 5158.2,3692.9 5152.1,3696.1 5145.7,3698.6 5139.1,3700.3 5132.3,3701.3 5125.4,3701.5 5118.6,3700.9 5111.9,3699.5 5105.4,3697.4 5099.1,3694.6 5093.3,3691 5087.8,3686.8 5082.9,3682.1 5078.6,3676.8 5074.9,3671 5071.9,3664.8 5069.6,3658.4 5068,3651.7 5067.2,3644.9 5067.2,3638
  lines w10: 3000,4200.8 3000.4,4169.9 3001.6,4139 3003.6,4108.1 3006.4,4077.3 3009.9,4046.6 3014.3,4016 3019.5,3985.5 3025.4,3955.2 3032.1,3925 3039.6,3895 3047.9,3865.2 3056.9,3835.6 3066.7,3806.3 3077.2,3777.2 3088.5,3748.4 3100.5,3719.9 3113.2,3691.8 3126.7,3663.9 3140.9,3636.4 3155.8,3609.3 3171.3,3582.6 3187.6,3556.3 3204.5,3530.5 3222.1,3505 3240.4,3480.1 3259.2,3455.6 3278.7,3431.6 3298.8,3408.1 3319.5,3385.1 3340.8,3362.7 3362.7,3340.8 3385.1,3319.5 3408.1,3298.8 3431.6,3278.7 3455.6,3259.2 3480.1,3240.4 3505,3222.1 3530.5,3204.5 3556.3,3187.6 3582.6,3171.3 3609.3,3155.8 3636.4,3140.9 3663.9,3126.7 3691.8,3113.2 3719.9,3100.5 3748.4,3088.5 3777.2,3077.2 3806.3,3066.7 3835.6,3056.9 3865.2,3047.9 3895,3039.6 3925,3032.1 3955.2,3025.4 3985.5,3019.5 4016,3014.3 4046.6,3009.9 4077.3,3006.4 4108.1,3003.6 4139,3001.6 4169.9,3000.4 4200.8,3000 4231.7,3000.4 4262.6,3001.6 4293.5,3003.6 4324.3,3006.4 4355,3009.9 4385.6,3014.3 4416.1,3019.5 4446.4,3025.4 4476.6,3032.1 4506.6,3039.6 4536.4,3047.9 4566,3056.9 4595.3,3066.7 4624.4,3077.2 4653.2,3088.5 4681.6,3100.5 4709.8,3113.2 4737.7,3126.7 4765.1,3140.9 4792.2,3155.8 4818.9,3171.3 4845.2,3187.6 4871.1,3204.5 4896.5,3222.1 4921.5,3240.4 4946,3259.2 4970,3278.7 4993.5,3298.8 5016.5,3319.5 5038.9,3340.8 5060.7,3362.7 5082,3385.1 5102.7,3408.1 5122.8,3431.6 5142.3,3455.6 5161.2,3480.1 5179.5,3505 5197.1,3530.5 5214,3556.3 5230.2,3582.6 5245.8,3609.3 5260.7,3636.4 5274.9,3663.9 5288.3,3691.8 5301.1,3719.9 5313.1,3748.4 5324.4,3777.2 5334.9,3806.3 5344.7,3835.6 5353.7,3865.2 5362,3895 5369.5,3925 5376.2,3955.2 5382.1,3985.5 5387.3,4016 5391.6,4046.6 5395.2,4077.3 5398,4108.1 5400,4139 5401.2,4169.9 5401.6,4200.8 5401.2,4231.7 5400,4262.6 5398,4293.5 5395.2,4324.3 5391.6,4355 5387.3,4385.6 5382.1,4416.1 5376.2,4446.4 5369.5,4476.6 5362,4506.6 5353.7,4536.4 5344.7,4566 5334.9,4595.3 5324.4,4624.4 5313.1,4653.2 5301.1,4681.6 5288.3,4709.8 5274.9,4737.7 5260.7,4765.1 5245.8,4792.2 5230.2,4818.9 5214,4845.2 5197.1,4871.1 5179.5,4896.5 5161.2,4921.5 5142.3,4946 5122.8,4970 5102.7,4993.5 5082,5016.5 5060.7,5038.9 5038.9,5060.7 5016.5,5082 4993.5,5102.7 4970,5122.8 4946,5142.3 4921.5,5161.2 4896.5,5179.5 4871.1,5197.1 4845.2,5214 4818.9,5230.2 4792.2,5245.8 4765.1,5260.7 4737.7,5274.9 4709.8,5288.3 4681.6,5301.1 4653.2,5313.1 4624.4,5324.4 4595.3,5334.9 4566,5344.7 4536.4,5353.7 4506.6,5362 4476.6,5369.5 4446.4,5376.2 4416.1,5382.1 4385.6,5387.3 4355,5391.6 4324.3,5395.2 4293.5,5398 4262.6,5400 4231.7,5401.2 4200.8,5401.6 4169.9,5401.2 4139,5400 4108.1,5398 4077.3,5395.2 4046.6,5391.6 4016,5387.3 3985.5,5382.1 3955.2,5376.2 3925,5369.5 3895,5362 3865.2,5353.7 3835.6,5344.7 3806.3,5334.9 3777.2,5324.4 3748.4,5313.1 3719.9,5301.1 3691.8,5288.3 3663.9,5274.9 3636.4,5260.7 3609.3,5245.8 3582.6,5230.2 3556.3,5214 3530.5,5197.1 3505,5179.5 3480.1,5161.2 3455.6,5142.3 3431.6,5122.8 3408.1,5102.7 3385.1,5082 3362.7,5060.7 3340.8,5038.9 3319.5,5016.5 3298.8,4993.5 3278.7,4970 3259.2,4946 3240.4,4921.5 3222.1,4896.5 3204.5,4871.1 3187.6,4845.2 3171.3,4818.9 3155.8,4792.2 3140.9,4765.1 3126.7,4737.7 3113.2,4709.8 3100.5,4681.6 3088.5,4653.2 3077.2,4624.4 3066.7,4595.3 3056.9,4566 3047.9,4536.4 3039.6,4506.6 3032.1,4476.6 3025.4,4446.4 3019.5,4416.1 3014.3,4385.6 3009.9,4355 3006.4,4324.3 3003.6,4293.5 3001.6,4262.6 3000.4,4231.7 3000,4200.8

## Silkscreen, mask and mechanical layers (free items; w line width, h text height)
Top Silkscreen Layer:
  drawing of 308 lines, arcs and shapes, not listed
  text "WYVERN-E r7.4" at 3676.5,5150.3 h98.4
Bottom Silkscreen Layer:
  drawing of 308 lines, arcs and shapes, not listed
  text "WYVERN-E r7.4" at 4623.8,5146.9 h118.1
Mechanical Layer:
  drawing of 220 lines, arcs and shapes, not listed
